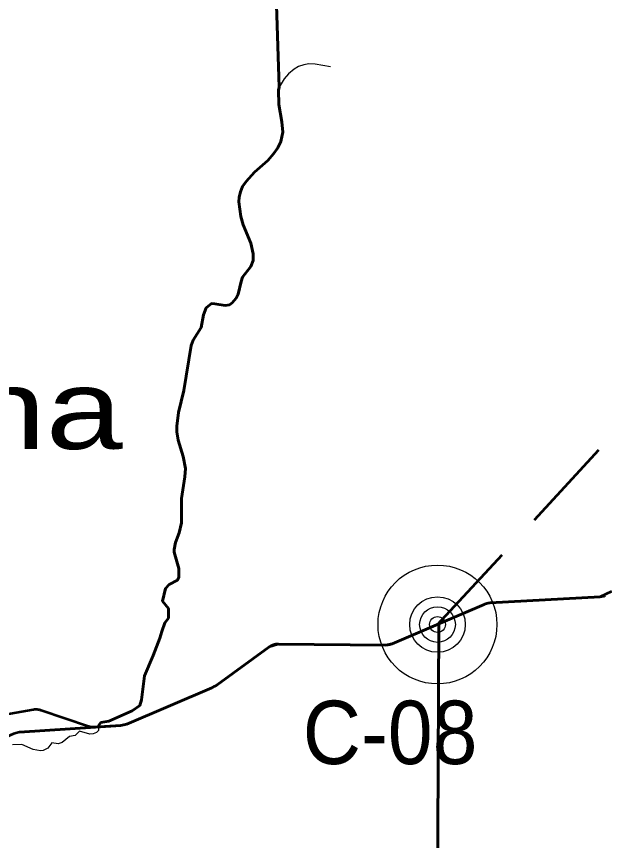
# Model space of a CAD drawing. Extents: x -1643653 to 4543381, y 1624270 to 13878484.
# Drawn here: x 633310 to 637017, y 8968166 to 8973365 of the extents above; entities that cross this region are included whole.
import ezdxf

# ---------------------------------------------------------------- set-up
doc = ezdxf.new("R2010")
doc.units = 0
doc.header["$LTSCALE"] = 200
doc.linetypes.add('MEDIUM_DASHED', pattern=[4.5, 3, -1.5])
for name, color, linetype, lineweight in [('1', 7, 'Continuous', 13), ('15', 7, 'Continuous', 25), ('24', 7, 'Continuous', 25), ('27', 7, 'Continuous', 53), ('28', 7, 'Continuous', 53), ('29', 7, 'Continuous', 13), ('60', 7, 'Continuous', 53)]:
    doc.layers.add(name, color=color, linetype=linetype, lineweight=lineweight)
doc.layers.add('63', color=7, linetype='Continuous')

msp = doc.modelspace()

# ---------------------------------------------------------------- linework, layer by layer
at = {"layer": '1', "lineweight": 25}
msp.add_spline([(814781, 9009175.5), (814787.2, 9009173.4), (814796.9, 9009173.4), (814799.4, 9009172.4), (814805.1, 9009174.5), (814805.6, 9009176.5), (814811.7, 9009179.5), (814811.7, 9009179.5), (814801.5, 9009181), (814790.7, 9009181.5), (814784.1, 9009183.1), (814777.4, 9009185.1), (814778.4, 9009175.5)], degree=3, dxfattribs=at)
at = {"layer": '15'}
for radius in [375, 175, 112.5, 50]:
    msp.add_circle((635964.2, 8969529.1), radius, dxfattribs=at)
at = {"layer": '24'}
for points in [[(635289.1, 8973046.9), (635193.3, 8973064.8), (635152.3, 8973065.7), (635121.8, 8973060.6), (635088.4, 8973049.6), (635061.3, 8973033.5), (635024.5, 8973002.4), (634997.2, 8972972.3), (634966.1, 8972918.2), (634961, 8972900.1), (634963.3, 8972809), (634982.5, 8972700.9), (634988.3, 8972634.8), (634977.1, 8972576.7), (634957, 8972536.6), (634931, 8972498.5), (634893.6, 8972457.3), (634810.8, 8972383.1), (634757.5, 8972324.9), (634734.8, 8972291.8), (634721.1, 8972258.8), (634713.2, 8972225.7), (634711, 8972195.6), (634723.7, 8972103.5), (634738.5, 8972051.5), (634787.3, 8971934.3), (634802.1, 8971867.3), (634801, 8971826.2), (634787, 8971787.1), (634735.3, 8971720.9), (634725.3, 8971693.9), (634707.4, 8971613.7), (634694.8, 8971588.7), (634670.6, 8971557.6), (634653, 8971546.5), (634625.3, 8971541.5), (634559.7, 8971552.4), (634539.5, 8971553.4), (634505.6, 8971527.3), (634489.3, 8971482.2), (634473.5, 8971402), (634424.6, 8971322.8), (634411, 8971288.8), (634363.8, 8971005.2), (634331.5, 8970867), (634319.9, 8970779.8), (634321.1, 8970743.8), (634328.9, 8970692.7), (634361.6, 8970589.6), (634374.7, 8970513.5), (634371.4, 8970461.4), (634350, 8970323.2), (634349.1, 8970169.9), (634336.1, 8970107.8), (634312.2, 8970046.7), (634303.6, 8970002.6), (634304.6, 8969985.6), (634333.8, 8969882.4), (634332.9, 8969828.3), (634324.3, 8969808.3), (634272.2, 8969782.2), (634248.5, 8969757.1), (634230.1, 8969676), (634268.6, 8969630), (634268.6, 8969569.3)], [(634268.6, 8969569.3), (634244.3, 8969539), (634226.1, 8969484.3), (634214, 8969441.9), (634171.5, 8969332.7), (634116.8, 8969205.3), (634098.6, 8969053.6), (634086.5, 8969017.2), (634039.3, 8968984.8)], [(634039.3, 8968984.8), (633892.2, 8968920.1), (633841.2, 8968911.2), (633829, 8968894.2), (633826.5, 8968860.1), (633814.7, 8968848.1), (633792.7, 8968839.1), (633772.6, 8968838), (633707.3, 8968856), (633679.2, 8968828.9), (633643, 8968822.8), (633597.4, 8968783.7), (633572.7, 8968776.6), (633532.2, 8968781.6), (633506.6, 8968748.5), (633477, 8968733.4), (633461.8, 8968732.4), (633415.1, 8968740.3), (633342.3, 8968771.2), (633285, 8968769.1)]]:
    msp.add_lwpolyline(points, dxfattribs=at)
at = {"layer": '27'}
for p, q in [((634966.1, 8972918.2), (634685, 8981342.6)), ((634685, 8981342.6), (634966.1, 8972918.2))]:
    msp.add_line(p, q, dxfattribs=at)
at = {"layer": '27', "linetype": 'MEDIUM_DASHED'}
msp.add_lwpolyline([(635964.2, 8969529.1), (637603, 8971301.5), (637574.9, 8971517.7), (637532.7, 8971754.1), (637479.5, 8971869.8), (637175.7, 8972061.2), (637248.8, 8972413.1), (637400.7, 8972469.4), (637448.6, 8972382.1), (637594.8, 8972289.2), (637825.5, 8972460.9), (637870.5, 8972663.6), (637721.4, 8972697.4), (637707.4, 8972753.7), (637800.2, 8972835.3), (637969, 8972959.1), (637848, 8973057.7), (637898.7, 8973097.1), (638033.7, 8973111.1), (638109.6, 8973169.1), (638137.8, 8973242.3), (638098.4, 8973371.8)], dxfattribs=at)
at = {"layer": '27'}
for points in [[(634268.6, 8969569.3), (634268.6, 8969630), (634230.1, 8969676), (634248.5, 8969757.1), (634272.2, 8969782.2), (634324.3, 8969808.3), (634332.9, 8969828.3), (634333.8, 8969882.4), (634304.6, 8969985.6), (634303.6, 8970002.6), (634312.2, 8970046.7), (634336.1, 8970107.8), (634349.1, 8970169.9), (634350, 8970323.2), (634371.4, 8970461.4), (634374.7, 8970513.5), (634361.6, 8970589.6), (634328.9, 8970692.7), (634321.1, 8970743.8), (634319.9, 8970779.8), (634331.5, 8970867), (634363.8, 8971005.2), (634411, 8971288.8), (634424.6, 8971322.8), (634473.5, 8971402), (634489.3, 8971482.2), (634505.6, 8971527.3), (634539.5, 8971553.4), (634559.7, 8971552.4), (634625.3, 8971541.5), (634653, 8971546.5), (634670.6, 8971557.6), (634694.8, 8971588.7), (634707.4, 8971613.7), (634725.3, 8971693.9), (634735.3, 8971720.9), (634787, 8971787.1), (634801, 8971826.2), (634802.1, 8971867.3), (634787.3, 8971934.3), (634738.5, 8972051.5), (634723.7, 8972103.5), (634711, 8972195.6), (634713.2, 8972225.7), (634721.1, 8972258.8), (634734.8, 8972291.8), (634757.5, 8972324.9), (634810.8, 8972383.1), (634893.6, 8972457.3), (634931, 8972498.5), (634957, 8972536.6), (634977.1, 8972576.7), (634988.3, 8972634.8), (634982.5, 8972700.9), (634963.3, 8972809), (634961, 8972900.1), (634966.1, 8972918.2)], [(634966.1, 8972918.2), (634961, 8972900.1), (634963.3, 8972809), (634982.5, 8972700.9), (634988.3, 8972634.8), (634977.1, 8972576.7), (634957, 8972536.6), (634931, 8972498.5), (634893.6, 8972457.3), (634810.8, 8972383.1), (634757.5, 8972324.9), (634734.8, 8972291.8), (634721.1, 8972258.8), (634713.2, 8972225.7), (634711, 8972195.6), (634723.7, 8972103.5), (634738.5, 8972051.5), (634787.3, 8971934.3), (634802.1, 8971867.3), (634801, 8971826.2), (634787, 8971787.1), (634735.3, 8971720.9), (634725.3, 8971693.9), (634707.4, 8971613.7), (634694.8, 8971588.7), (634670.6, 8971557.6), (634653, 8971546.5), (634625.3, 8971541.5), (634559.7, 8971552.4), (634539.5, 8971553.4), (634505.6, 8971527.3), (634489.3, 8971482.2), (634473.5, 8971402), (634424.6, 8971322.8), (634411, 8971288.8), (634363.8, 8971005.2), (634331.5, 8970867), (634319.9, 8970779.8), (634321.1, 8970743.8), (634328.9, 8970692.7), (634361.6, 8970589.6), (634374.7, 8970513.5), (634371.4, 8970461.4), (634350, 8970323.2), (634349.1, 8970169.9), (634336.1, 8970107.8), (634312.2, 8970046.7), (634303.6, 8970002.6), (634304.6, 8969985.6), (634333.8, 8969882.4), (634332.9, 8969828.3), (634324.3, 8969808.3), (634272.2, 8969782.2), (634248.5, 8969757.1), (634230.1, 8969676), (634268.6, 8969630), (634268.6, 8969569.3)], [(637019.6, 8969709.3), (637016.9, 8969708.4), (637014.2, 8969707.5), (637011.5, 8969706.7), (637008.8, 8969706), (637006, 8969705.4), (637003.2, 8969704.8), (637000.4, 8969704.3), (636997.6, 8969703.9), (636994.8, 8969703.6), (636992, 8969703.3), (636990.3, 8969703.2), (636296.8, 8969664.9), (636293.8, 8969664.7), (636290.8, 8969664.4), (636287.8, 8969664), (636284.8, 8969663.6), (636281.9, 8969663.1), (636279, 8969662.5), (636276, 8969661.8), (636273.1, 8969661), (636270.2, 8969660.2), (636267.4, 8969659.3), (636264.5, 8969658.3), (636261.7, 8969657.2), (636258.9, 8969656.1), (636258.5, 8969655.9), (635971.9, 8969532.8)], [(637019.6, 8969709.3), (637016.9, 8969708.4), (637014.2, 8969707.5), (637011.5, 8969706.7), (637008.8, 8969706), (637006, 8969705.4), (637003.2, 8969704.8), (637000.4, 8969704.3), (636997.6, 8969703.9), (636994.8, 8969703.6), (636992, 8969703.3), (636990.3, 8969703.2), (636296.8, 8969664.9), (636293.8, 8969664.7), (636290.8, 8969664.4), (636287.8, 8969664), (636284.8, 8969663.6), (636281.9, 8969663.1), (636279, 8969662.5), (636276, 8969661.8), (636273.1, 8969661), (636270.2, 8969660.2), (636267.4, 8969659.3), (636264.5, 8969658.3), (636261.7, 8969657.2), (636258.9, 8969656.1), (636258.5, 8969655.9), (635971.9, 8969532.8)], [(634039.3, 8968984.8), (634086.5, 8969017.2), (634098.6, 8969053.6), (634116.8, 8969205.3), (634171.5, 8969332.7), (634214, 8969441.9), (634226.1, 8969484.3), (634244.3, 8969539), (634268.6, 8969569.3)], [(634268.6, 8969569.3), (634244.3, 8969539), (634226.1, 8969484.3), (634214, 8969441.9), (634171.5, 8969332.7), (634116.8, 8969205.3), (634098.6, 8969053.6), (634086.5, 8969017.2), (634039.3, 8968984.8)], [(633530.9, 8956745.3), (633642.5, 8958653.7), (635936.8, 8962048.5), (635971.9, 8969532.8)], [(635971.9, 8969532.8), (635936.8, 8962048.5), (633642.5, 8958653.7), (633530.9, 8956745.3), (633530.9, 8956745.3)], [(635971.9, 8969532.8), (635679.4, 8969407.1), (635676.8, 8969406), (635674.1, 8969405), (635671.4, 8969404.1), (635668.7, 8969403.2), (635666, 8969402.5), (635663.3, 8969401.8), (635660.5, 8969401.1), (635657.8, 8969400.6), (635655, 8969400.1), (635652.2, 8969399.7), (635649.3, 8969399.4), (635646.5, 8969399.2), (635643.7, 8969399.1), (635640.9, 8969399), (635638.9, 8969399), (635638.9, 8969399), (634961.2, 8969405.5), (634961.2, 8969405.5), (634958.4, 8969405.4), (634955.6, 8969405.3), (634952.7, 8969405.2), (634949.9, 8969404.9), (634947.1, 8969404.6), (634944.3, 8969404.2), (634941.5, 8969403.7), (634938.8, 8969403.1), (634936, 8969402.5), (634933.3, 8969401.7), (634930.6, 8969400.9), (634927.9, 8969400.1), (634925.2, 8969399.1), (634922.6, 8969398.1), (634920, 8969397), (634917.4, 8969395.8), (634914.8, 8969394.6), (634912.3, 8969393.2), (634909.9, 8969391.8), (634907.5, 8969390.4), (634905.1, 8969388.8), (634902.7, 8969387.3), (634901.5, 8969386.3), (634575, 8969149.1), (634571.9, 8969146.9), (634568.8, 8969144.8), (634565.6, 8969142.7), (634562.4, 8969140.7), (634559.2, 8969138.8), (634555.9, 8969137), (634552.6, 8969135.2), (634549.2, 8969133.5), (634545.8, 8969131.9), (634542.4, 8969130.3), (634540.4, 8969129.4), (634005.7, 8968901.1), (634002.8, 8968899.9), (634000, 8968898.8), (633997.1, 8968897.8), (633994.1, 8968896.8), (633991.2, 8968896), (633988.2, 8968895.2), (633985.2, 8968894.5), (633982.2, 8968893.8), (633979.2, 8968893.3)], [(635971.9, 8969532.8), (635679.4, 8969407.1), (635676.8, 8969406), (635674.1, 8969405), (635671.4, 8969404.1), (635668.7, 8969403.2), (635666, 8969402.5), (635663.3, 8969401.8), (635660.5, 8969401.1), (635657.8, 8969400.6), (635655, 8969400.1), (635652.2, 8969399.7), (635649.3, 8969399.4), (635646.5, 8969399.2), (635643.7, 8969399.1), (635640.9, 8969399), (635638.9, 8969399), (635638.9, 8969399), (634961.2, 8969405.5), (634961.2, 8969405.5), (634958.4, 8969405.4), (634955.6, 8969405.3), (634952.7, 8969405.2), (634949.9, 8969404.9), (634947.1, 8969404.6), (634944.3, 8969404.2), (634941.5, 8969403.7), (634938.8, 8969403.1), (634936, 8969402.5), (634933.3, 8969401.7), (634930.6, 8969400.9), (634927.9, 8969400.1), (634925.2, 8969399.1), (634922.6, 8969398.1), (634920, 8969397), (634917.4, 8969395.8), (634914.8, 8969394.6), (634912.3, 8969393.2), (634909.9, 8969391.8), (634907.5, 8969390.4), (634905.1, 8969388.8), (634902.7, 8969387.3), (634901.5, 8969386.3), (634575, 8969149.1), (634571.9, 8969146.9), (634568.8, 8969144.8), (634565.6, 8969142.7), (634562.4, 8969140.7), (634559.2, 8969138.8), (634555.9, 8969137), (634552.6, 8969135.2), (634549.2, 8969133.5), (634545.8, 8969131.9), (634542.4, 8969130.3), (634540.4, 8969129.4), (634005.7, 8968901.1), (634002.8, 8968899.9), (634000, 8968898.8), (633997.1, 8968897.8), (633994.1, 8968896.8), (633991.2, 8968896), (633988.2, 8968895.2), (633985.2, 8968894.5), (633982.2, 8968893.8), (633979.2, 8968893.3)], [(633828.1, 8968882.6), (633802.6, 8968880.9), (633799.8, 8968880.7), (633797, 8968880.7), (633794.1, 8968880.7), (633791.3, 8968880.8), (633788.5, 8968880.9), (633785.7, 8968881.2), (633782.9, 8968881.5), (633780.1, 8968881.9), (633777.3, 8968882.4), (633774.5, 8968883), (633771.8, 8968883.6), (633769, 8968884.4), (633766.3, 8968885.2), (633763.9, 8968885.9), (633464.2, 8968987.2), (633461.5, 8968988.1), (633458.8, 8968988.9), (633456.1, 8968989.6), (633453.3, 8968990.2), (633450.6, 8968990.8), (633447.8, 8968991.3), (633445, 8968991.7), (633442.2, 8968992), (633439.3, 8968992.2), (633436.5, 8968992.4), (633433.7, 8968992.5), (633430.9, 8968992.5), (633428, 8968992.4), (633425.2, 8968992.2), (633422.4, 8968992), (633419.6, 8968991.7), (633416.8, 8968991.3), (633414.9, 8968991), (632688.6, 8968863)], [(633828.1, 8968882.6), (633802.6, 8968880.9), (633799.8, 8968880.7), (633797, 8968880.7), (633794.1, 8968880.7), (633791.3, 8968880.8), (633788.5, 8968880.9), (633785.7, 8968881.2), (633782.9, 8968881.5), (633780.1, 8968881.9), (633777.3, 8968882.4), (633774.5, 8968883), (633771.8, 8968883.6), (633769, 8968884.4), (633766.3, 8968885.2), (633763.9, 8968885.9), (633464.2, 8968987.2), (633461.5, 8968988.1), (633458.8, 8968988.9), (633456.1, 8968989.6), (633453.3, 8968990.2), (633450.6, 8968990.8), (633447.8, 8968991.3), (633445, 8968991.7), (633442.2, 8968992), (633439.3, 8968992.2), (633436.5, 8968992.4), (633433.7, 8968992.5), (633430.9, 8968992.5), (633428, 8968992.4), (633425.2, 8968992.2), (633422.4, 8968992), (633419.6, 8968991.7), (633416.8, 8968991.3), (633414.9, 8968991), (632688.6, 8968863)], [(633828.1, 8968882.6), (633829, 8968894.2), (633841.2, 8968911.2), (633892.2, 8968920.1), (634039.3, 8968984.8)], [(634039.3, 8968984.8), (633892.2, 8968920.1), (633841.2, 8968911.2), (633829, 8968894.2), (633828.1, 8968882.6)], [(633979.2, 8968893.3), (633976.2, 8968892.8), (633973.2, 8968892.4), (633970.1, 8968892.1), (633967.3, 8968891.9), (633828.1, 8968882.6)], [(633979.2, 8968893.3), (633976.2, 8968892.8), (633973.2, 8968892.4), (633970.1, 8968892.1), (633967.3, 8968891.9), (633828.1, 8968882.6)]]:
    msp.add_lwpolyline(points, dxfattribs=at)
at = {"layer": '28'}
for p, q in [((635679.4, 8969407.1), (636258.5, 8969655.9)), ((636296.8, 8969664.9), (636990.3, 8969703.2)), ((634961.2, 8969405.5), (635638.9, 8969399)), ((634575, 8969149.1), (634901.5, 8969386.3)), ((634005.7, 8968901.1), (634540.4, 8969129.4)), ((633328.7, 8968849.2), (633967.3, 8968891.9))]:
    msp.add_line(p, q, dxfattribs=at)
msp.add_lwpolyline([(637060.8, 8969738.2), (636990.3, 8969703.2), (636296.8, 8969664.9), (636258.5, 8969655.9), (635679.4, 8969407.1), (635638.9, 8969399), (634961.2, 8969405.5), (634901.5, 8969386.3), (634575, 8969149.1), (634540.4, 8969129.4), (634005.7, 8968901.1), (633967.3, 8968891.9), (633328.7, 8968849.2), (633290.6, 8968839.6), (632717.1, 8968577.3), (632679, 8968566.9), (632095, 8968504.8), (632057.1, 8968494), (631573.9, 8968260.4), (631535.9, 8968251.7), (631226.3, 8968251.7)], dxfattribs=at)
msp.add_lwpolyline([(637060.8, 8969738.2), (636990.3, 8969703.2), (636296.8, 8969664.9), (636258.5, 8969655.9), (635679.4, 8969407.1), (635638.9, 8969399), (634961.2, 8969405.5), (634901.5, 8969386.3), (634575, 8969149.1), (634540.4, 8969129.4), (634005.7, 8968901.1), (633967.3, 8968891.9), (633328.7, 8968849.2), (633290.6, 8968839.6), (632717.1, 8968577.3), (632679, 8968566.9), (632095, 8968504.8), (632057.1, 8968494), (631573.9, 8968260.4), (631535.9, 8968251.7), (631226.3, 8968251.7)], dxfattribs=at)
at = {"layer": '29', "lineweight": 53}
for p, q in [((635679.4, 8969407.1), (636258.5, 8969655.9)), ((636296.8, 8969664.9), (636990.3, 8969703.2)), ((634961.2, 8969405.5), (635638.9, 8969399)), ((634575, 8969149.1), (634901.5, 8969386.3)), ((634005.7, 8968901.1), (634540.4, 8969129.4)), ((633328.7, 8968849.2), (633967.3, 8968891.9))]:
    msp.add_line(p, q, dxfattribs=at)
at = {"layer": '60'}
for points in [[(637019.6, 8969709.3), (637016.9, 8969708.4), (637014.2, 8969707.5), (637011.5, 8969706.7), (637008.8, 8969706), (637006, 8969705.4), (637003.2, 8969704.8), (637000.4, 8969704.3), (636997.6, 8969703.9), (636994.8, 8969703.6), (636992, 8969703.3), (636990.3, 8969703.2), (636296.8, 8969664.9), (636293.8, 8969664.7), (636290.8, 8969664.4), (636287.8, 8969664), (636284.8, 8969663.6), (636281.9, 8969663.1), (636279, 8969662.5), (636276, 8969661.8), (636273.1, 8969661), (636270.2, 8969660.2), (636267.4, 8969659.3), (636264.5, 8969658.3), (636261.7, 8969657.2), (636258.9, 8969656.1), (636258.5, 8969655.9), (635679.4, 8969407.1), (635676.8, 8969406), (635674.1, 8969405), (635671.4, 8969404.1), (635668.7, 8969403.2), (635666, 8969402.5), (635663.3, 8969401.8), (635660.5, 8969401.1), (635657.8, 8969400.6), (635655, 8969400.1), (635652.2, 8969399.7), (635649.3, 8969399.4), (635646.5, 8969399.2), (635643.7, 8969399.1), (635640.9, 8969399), (635638.9, 8969399), (635638.9, 8969399), (634961.2, 8969405.5), (634961.2, 8969405.5), (634958.4, 8969405.4), (634955.6, 8969405.3), (634952.7, 8969405.2), (634949.9, 8969404.9), (634947.1, 8969404.6), (634944.3, 8969404.2), (634941.5, 8969403.7), (634938.8, 8969403.1), (634936, 8969402.5), (634933.3, 8969401.7), (634930.6, 8969400.9), (634927.9, 8969400.1), (634925.2, 8969399.1), (634922.6, 8969398.1), (634920, 8969397), (634917.4, 8969395.8), (634914.8, 8969394.6), (634912.3, 8969393.2), (634909.9, 8969391.8), (634907.5, 8969390.4), (634905.1, 8969388.8), (634902.7, 8969387.3), (634901.5, 8969386.3), (634575, 8969149.1), (634571.9, 8969146.9), (634568.8, 8969144.8), (634565.6, 8969142.7), (634562.4, 8969140.7), (634559.2, 8969138.8), (634555.9, 8969137), (634552.6, 8969135.2), (634549.2, 8969133.5), (634545.8, 8969131.9), (634542.4, 8969130.3), (634540.4, 8969129.4), (634005.7, 8968901.1), (634002.8, 8968899.9), (634000, 8968898.8), (633997.1, 8968897.8), (633994.1, 8968896.8), (633991.2, 8968896), (633988.2, 8968895.2), (633985.2, 8968894.5), (633982.2, 8968893.8), (633979.2, 8968893.3)], [(633979.2, 8968893.3), (633976.2, 8968892.8), (633973.2, 8968892.4), (633970.1, 8968892.1), (633967.3, 8968891.9), (633802.6, 8968880.9), (633799.8, 8968880.7), (633797, 8968880.7), (633794.1, 8968880.7), (633791.3, 8968880.8), (633788.5, 8968880.9), (633785.7, 8968881.2), (633782.9, 8968881.5), (633780.1, 8968881.9), (633777.3, 8968882.4), (633774.5, 8968883), (633771.8, 8968883.6), (633769, 8968884.4), (633766.3, 8968885.2), (633763.9, 8968885.9), (633464.2, 8968987.2), (633461.5, 8968988.1), (633458.8, 8968988.9), (633456.1, 8968989.6), (633453.3, 8968990.2), (633450.6, 8968990.8), (633447.8, 8968991.3), (633445, 8968991.7), (633442.2, 8968992), (633439.3, 8968992.2), (633436.5, 8968992.4), (633433.7, 8968992.5), (633430.9, 8968992.5), (633428, 8968992.4), (633425.2, 8968992.2), (633422.4, 8968992), (633419.6, 8968991.7), (633416.8, 8968991.3), (633414.9, 8968991), (632688.6, 8968863)]]:
    msp.add_lwpolyline(points, dxfattribs=at)

# ---------------------------------------------------------------- texts
at = {"layer": '15', "width": 0.95}
msp.add_text('C-08', height=400, dxfattribs=at).set_placement((635114.7, 8968648.5))
at = {"layer": '63', "width": 1.3}
msp.add_text(' 6683.15 ha', height=500, dxfattribs=at).set_placement((629386.7, 8970636.6))

doc.saveas('drawing.dxf')
